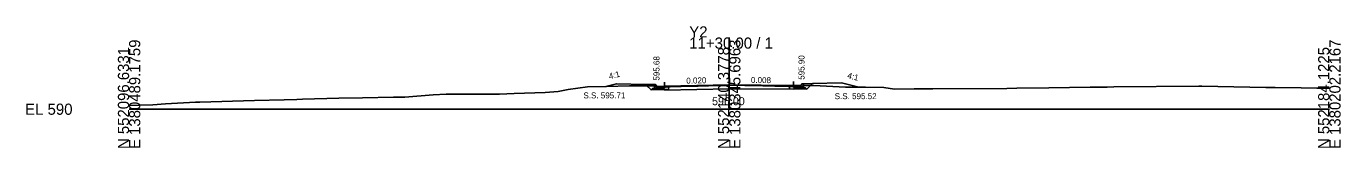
# Model space of a CAD drawing. Extents: x -26 to 303, y -10 to 2047.
# Drawn here: x -25.7 to 302.8, y 990.3 to 1020.8 of the extents above; entities that cross this region are included whole.
import ezdxf

# ---------------------------------------------------------------- set-up
doc = ezdxf.new("R2010")
doc.units = 0
for name, color, linetype in [('Exist Cross Section Cell', 7, 'Continuous'), ('Exist XS Center Line Elevation Label', 7, 'Continuous'), ('Exist XS Ground Line', 7, 'Continuous'), ('Prop XS Dump Level', 7, 'Continuous'), ('Prop XS Earthwork Shape', 7, 'Continuous'), ('Prop XS EOT Tick Mark', 7, 'Continuous'), ('Prop XS Finish Grade', 7, 'Continuous'), ('Prop XS Finish Grade CurbGutter', 7, 'Continuous'), ('Prop XS Finish Grade Earthwork', 7, 'Continuous'), ('Prop XS Finish Grade Pavement', 7, 'Continuous'), ('Prop XS Hydro Elevations', 7, 'Continuous'), ('Prop XS Pvmt Edge Slope', 7, 'Continuous'), ('Prop XS SE Text', 7, 'Continuous'), ('Prop XS Side Slope Text', 7, 'Continuous'), ('Prop XS SS Elevation Text', 7, 'Continuous'), ('Prop XS Subgrade CurbGutter', 7, 'Continuous'), ('Prop XS Subgrade Earthwork', 7, 'Continuous')]:
    doc.layers.add(name, color=color, linetype=linetype)

msp = doc.modelspace()

# ---------------------------------------------------------------- linework, layer by layer
at = {"layer": 'Exist Cross Section Cell'}
for p, q in [((150, 1000), (150, 1018)), ((0, 1000), (150, 1000)), ((150, 1000), (300, 1000))]:
    msp.add_line(p, q, dxfattribs=at)
at = {"layer": 'Exist XS Ground Line'}
for p, q in [((109.77, 1004.91), (114.6, 1005.63)), ((114.6, 1005.63), (119.36, 1005.72)), ((119.36, 1005.72), (125.06, 1005.83)), ((125.06, 1005.83), (130.01, 1005.87)), ((130.01, 1005.87), (131, 1005.89)), ((131, 1005.89), (131.99, 1005.53)), ((131.99, 1005.53), (132.83, 1005.55)), ((132.83, 1005.55), (133.68, 1005.57)), ((133.68, 1005.57), (134.49, 1005.6)), ((134.49, 1005.6), (135.23, 1005.63)), ((135.23, 1005.63), (136.98, 1005.69)), ((136.98, 1005.69), (137.99, 1005.72)), ((137.99, 1005.72), (139.6, 1005.76)), ((139.6, 1005.76), (141.26, 1005.8)), ((141.26, 1005.8), (142.21, 1005.82)), ((142.21, 1005.82), (144, 1005.85)), ((144, 1005.85), (144.83, 1005.87)), ((144.83, 1005.87), (145.99, 1005.91)), ((145.99, 1005.91), (147.43, 1005.95)), ((147.43, 1005.95), (147.99, 1005.96)), ((147.99, 1005.96), (150.13, 1006)), ((150.13, 1006), (152.63, 1006)), ((152.63, 1006), (153.87, 1005.98)), ((153.87, 1005.98), (155.24, 1005.97)), ((155.24, 1005.97), (157.98, 1005.91)), ((157.98, 1005.91), (158.39, 1005.9)), ((158.39, 1005.9), (160.48, 1005.85)), ((160.48, 1005.85), (161.4, 1005.82)), ((161.4, 1005.82), (163.09, 1005.77)), ((163.09, 1005.77), (164.84, 1005.72)), ((164.84, 1005.72), (165.53, 1005.7)), ((165.53, 1005.7), (166.02, 1005.68)), ((166.02, 1005.68), (167.04, 1005.64)), ((167.04, 1005.64), (167.8, 1005.6)), ((167.8, 1005.6), (168.8, 1005.98)), ((168.8, 1005.98), (171.17, 1005.94)), ((171.17, 1005.94), (179.1, 1005.55)), ((179.1, 1005.55), (184.08, 1005.51)), ((184.08, 1005.51), (188.66, 1005.44)), ((188.66, 1005.44), (191.33, 1005.03)), ((221.9, 1005.27), (229.86, 1005.4)), ((229.86, 1005.4), (240.24, 1005.53)), ((240.24, 1005.53), (244.48, 1005.56)), ((244.48, 1005.56), (246.12, 1005.58)), ((246.12, 1005.58), (267.36, 1005.81)), ((267.36, 1005.81), (268.14, 1005.81)), ((268.14, 1005.81), (284.13, 1005.43)), ((284.13, 1005.43), (286.43, 1005.44)), ((286.43, 1005.44), (292.96, 1005.36)), ((292.96, 1005.36), (296.91, 1005.3)), ((17.68, 1001.78), (31.31, 1002.17)), ((31.31, 1002.17), (38.78, 1002.31)), ((38.78, 1002.31), (41.91, 1002.44)), ((41.91, 1002.44), (43.31, 1002.53)), ((43.31, 1002.53), (52.39, 1002.73)), ((52.39, 1002.73), (58.3, 1002.85)), ((58.3, 1002.85), (66.09, 1002.99)), ((66.09, 1002.99), (68.9, 1003.06)), ((68.9, 1003.06), (76.04, 1003.6)), ((76.04, 1003.6), (79.22, 1003.75)), ((79.22, 1003.75), (82.73, 1003.77)), ((82.73, 1003.77), (92.58, 1003.79)), ((92.58, 1003.79), (96.28, 1003.92)), ((96.28, 1003.92), (104, 1004.2)), ((104, 1004.2), (107.24, 1004.46)), ((107.24, 1004.46), (109.77, 1004.91)), ((191.33, 1005.03), (196.25, 1005.12)), ((196.25, 1005.12), (200.91, 1005.12)), ((200.91, 1005.12), (219.35, 1005.22)), ((219.35, 1005.22), (221.9, 1005.27)), ((296.91, 1005.3), (297.63, 1005.29)), ((297.63, 1005.29), (300, 1005.26)), ((0, 1000.93), (2.69, 1001.01)), ((2.69, 1001.01), (5.94, 1001.09)), ((5.94, 1001.09), (9.14, 1001.31)), ((9.14, 1001.31), (16.59, 1001.77)), ((16.59, 1001.77), (17.68, 1001.78))]:
    msp.add_line(p, q, dxfattribs=at)
at = {"layer": 'Prop XS Dump Level'}
for p, q in [((133.82, 1005.8), (150, 1006.13)), ((150, 1006.13), (166.07, 1005.99)), ((133.82, 1004.8), (150, 1005.13)), ((150, 1005.13), (166.07, 1004.99))]:
    msp.add_line(p, q, dxfattribs=at)
at = {"layer": 'Prop XS Earthwork Shape'}
for points in [[(119.14, 1005.71), (119.36, 1005.72), (125.06, 1005.83), (129.45, 1005.86), (129.08, 1006.23), (121.82, 1006.38)], [(129.45, 1005.86), (130.01, 1005.87), (131, 1005.89), (131.99, 1005.53), (132.83, 1005.55), (133.68, 1005.57), (134.49, 1005.6), (134.82, 1005.61), (134.82, 1004.91), (130.48, 1004.82)], [(168.8, 1005.98), (170.31, 1005.96), (169.4, 1005.05), (165.07, 1005.09), (165.07, 1005.71), (165.53, 1005.7), (166.02, 1005.68), (167.04, 1005.64), (167.8, 1005.6)], [(170.31, 1005.96), (170.79, 1006.44), (178.07, 1006.6), (182.36, 1005.52), (179.1, 1005.55), (171.17, 1005.94)]]:
    msp.add_lwpolyline(points, close=True, dxfattribs=at)
at = {"layer": 'Prop XS EOT Tick Mark'}
for p, q in [((133.82, 1005.8), (133.82, 1006.8)), ((166.07, 1005.99), (166.07, 1006.99))]:
    msp.add_line(p, q, dxfattribs=at)
at = {"layer": 'Prop XS Finish Grade'}
for p, q in [((131.32, 1006.18), (129.08, 1006.23)), ((168.57, 1006.4), (170.79, 1006.44))]:
    msp.add_line(p, q, dxfattribs=at)
at = {"layer": 'Prop XS Finish Grade CurbGutter'}
for p, q in [((131.32, 1006.18), (131.57, 1006.18)), ((131.57, 1006.18), (131.69, 1006.15)), ((131.78, 1006.06), (131.69, 1006.15)), ((131.85, 1005.81), (131.78, 1006.06)), ((131.94, 1005.72), (131.85, 1005.81)), ((132.07, 1005.7), (131.94, 1005.72)), ((133.82, 1005.8), (132.07, 1005.7)), ((166.07, 1005.99), (167.82, 1005.91)), ((167.82, 1005.91), (167.94, 1005.93)), ((167.94, 1005.93), (168.04, 1006.02)), ((168.04, 1006.02), (168.1, 1006.27)), ((168.1, 1006.27), (168.19, 1006.36)), ((168.32, 1006.4), (168.19, 1006.36)), ((168.57, 1006.4), (168.32, 1006.4))]:
    msp.add_line(p, q, dxfattribs=at)
at = {"layer": 'Prop XS Finish Grade Earthwork'}
for p, q in [((121.82, 1006.38), (119.14, 1005.71)), ((129.08, 1006.23), (121.82, 1006.38)), ((170.79, 1006.44), (178.07, 1006.6)), ((178.07, 1006.6), (182.36, 1005.52))]:
    msp.add_line(p, q, dxfattribs=at)
at = {"layer": 'Prop XS Finish Grade Pavement'}
for p, q in [((133.82, 1005.8), (150, 1006.13)), ((150, 1006.13), (166.07, 1005.99))]:
    msp.add_line(p, q, dxfattribs=at)
at = {"layer": 'Prop XS Pvmt Edge Slope'}
for p, q in [((168.57, 1005.39), (169.07, 1005.39)), ((169.07, 1005.39), (169.4, 1005.05)), ((130.82, 1005.16), (130.48, 1004.82)), ((131.32, 1005.17), (130.82, 1005.16))]:
    msp.add_line(p, q, dxfattribs=at)
at = {"layer": 'Prop XS Subgrade CurbGutter'}
for p, q in [((131.32, 1005.17), (131.32, 1006.18)), ((133.82, 1005.8), (133.82, 1005.22)), ((166.07, 1005.99), (166.07, 1005.41)), ((166.07, 1005.41), (168.57, 1005.39)), ((168.57, 1005.39), (168.57, 1006.4)), ((133.82, 1005.22), (131.32, 1005.17))]:
    msp.add_line(p, q, dxfattribs=at)
at = {"layer": 'Prop XS Subgrade Earthwork'}
for p, q in [((130.48, 1004.82), (129.08, 1006.23)), ((134.82, 1004.91), (134.82, 1005.61)), ((165.07, 1005.09), (165.07, 1005.71)), ((169.4, 1005.05), (170.79, 1006.44)), ((134.82, 1004.91), (130.48, 1004.82)), ((165.07, 1005.09), (169.4, 1005.05))]:
    msp.add_line(p, q, dxfattribs=at)

# ---------------------------------------------------------------- texts
at = {"layer": 'Exist Cross Section Cell'}
for s, p in [('Y2', (140, 1018)), ('11+30.00 / 1', (140, 1015.2)), ('EL 590', (-26, 998.6))]:
    msp.add_text(s, height=2.8, dxfattribs=at).set_placement(p)
for s, p in [('N 552096.6331', (0, 990)), ('E 1380489.1759', (2.8, 990)), ('N 552140.3778', (150, 990)), ('E 1380345.6963', (152.8, 990)), ('N 552184.1225', (300, 990)), ('E 1380202.2167', (302.8, 990))]:
    msp.add_text(s, height=2.8, rotation=90, dxfattribs=at).set_placement(p)
at = {"layer": 'Exist XS Center Line Elevation Label'}
msp.add_text('596.00', height=2, dxfattribs=at).set_placement((145.71, 1001))
at = {"layer": 'Prop XS Dump Level'}
for p in [(133.68, 1005.27), (166.02, 1005.38)]:
    msp.add_text('Eop', height=0.3, dxfattribs=at).set_placement(p)
at = {"layer": 'Prop XS Hydro Elevations'}
for s, p in [('595.68', (132.57, 1007.18)), ('595.90', (168.82, 1007.4))]:
    msp.add_text(s, height=1.5, rotation=90, dxfattribs=at).set_placement(p)
at = {"layer": 'Prop XS SE Text'}
for s, rotation, p in [('0.020', 1.1458, (139.28, 1006.41)), ('0.008', 359.5225, (155.42, 1006.58))]:
    msp.add_text(s, height=1.5, rotation=rotation, dxfattribs=at).set_placement(p)
at = {"layer": 'Prop XS Side Slope Text'}
for rotation, p in [(14.0362, (120.11, 1007.5)), (345.9638, (179.43, 1007.8))]:
    msp.add_text('4:1', height=1.5, rotation=rotation, dxfattribs=at).set_placement(p)
at = {"layer": 'Prop XS SS Elevation Text'}
for s, p in [('S.S. 595.71', (113.56, 1002.71)), ('S.S. 595.52', (176.36, 1002.52))]:
    msp.add_text(s, height=1.5, dxfattribs=at).set_placement(p)

doc.saveas('drawing.dxf')
